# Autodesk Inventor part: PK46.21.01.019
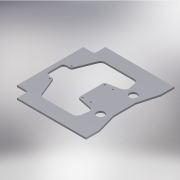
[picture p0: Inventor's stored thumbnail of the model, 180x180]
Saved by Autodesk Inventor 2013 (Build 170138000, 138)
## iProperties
Created: 2005-04
Part Number: PK46.21.01.019
Material: Steel, Mild
Document SubType Name: Modeling
Designer: salex
Manufacturer: Standard
Standards Organization: Custom
Density: 7.86 g/cm^3
Author: salex
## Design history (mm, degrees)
sketch "Эскиз1"
  geometry: L1 (0, 0)-(625, 0); L2 (625, 0)-(625, -120); L3 (625, -120)-(575, -300); L4 (575, -300)-(575, -500); L5 (0, 0)-(0, -100); L6 (0, -100)-(-100, -100); L7 (-100, -100)-(-100, -700); L8 (-60, -450)-(-60, -350); L9 (-30, -320)-(-5, -320); L10 (13.519, -307.552)-(79.848, -144.896); L11 (116.887, -120)-(381.959, -120); L12 (421.24, -152.446)-(432.521, -211.11); L13 (401.187, -257.867)-(290.027, -280.399); L14 (274, -300)-(274, -500); L15 (-32.529, -400)-(706.052, -400); L16 (401.187, -542.133)-(290.027, -519.601); L17 (421.24, -647.554)-(432.521, -588.89); L18 (116.887, -680)-(381.959, -680); L19 (0, -800)-(625, -800); L20 (625, -680)-(575, -500); L21 (0, -800)-(0, -700); L22 (0, -700)-(-100, -700); L23 (-30, -480)-(-5, -480); L24 (13.519, -492.448)-(79.848, -655.104); L25 (625, -800)-(625, -680); C1 r 6.5 at (294, -300); C2 r 6.5 at (294, -500); C3 r 35 at (505, -252); C4 r 35 at (505, -548); C5 r 6.5 at (-5, -300); C6 r 6.5 at (-5, -500); C7 r 6.5 at (368, -300); C8 r 6.5 at (368, -500); A1 r 30 centre (-30, -350) between (-30, -320) and (-60, -350); A2 r 20 centre (-5, -300) between (-5, -320) and (13.519, -307.552); A3 r 20 centre (294, -300) between (290.027, -280.399) and (274, -300); A4 r 40 centre (116.887, -160) between (116.887, -120) and (79.848, -144.896); A5 r 40 centre (381.959, -160) between (421.24, -152.446) and (381.959, -120); A6 r 40 centre (393.241, -218.664) between (401.187, -257.867) and (432.521, -211.11); A7 r 20 centre (294, -500) between (274, -500) and (290.027, -519.601); A8 r 40 centre (393.241, -581.336) between (432.521, -588.89) and (401.187, -542.133); A9 r 40 centre (116.887, -640) between (79.848, -655.104) and (116.887, -680); A10 r 40 centre (381.959, -640) between (381.959, -680) and (421.24, -647.554); A11 r 20 centre (-5, -500) between (13.519, -492.448) and (-5, -480); A12 r 30 centre (-30, -450) between (-60, -450) and (-30, -480); 6 further points
  constraints: 50 end point, 29 symmetric about line, 24 point on circle, 20 centre point, 12 point on line, 12 tangent, 6 equal radius, 6 parallel, 4 perpendicular, 2 coincident, 1 concentric, 1 horizontal, 9 other
  dimensions: "d0" = 725 distance between parallel lines of L2 L7; "d1" = 120 distance of L1.end L2.end; "d2" = 675 distance between parallel lines of L4 L7; "d3" = 300 distance from line of L3.end L1; "d4" = 100 distance of L1.start L5.end; "d5" = 100 distance of L5.end L6.end; "d6" = 325 distance of point (90, -120) point (415, -120); "d7" = 350 horizontal distance of point (440, -250) point (90, -120); "d9" = 800 diameter of L1 L15; "d10" = 560 diameter of L11 L15; "d12" = 20 radius of A2; "d13" = 20 radius of A3; "d15" = 13 diameter of C1 (= d14); "d19" = 130 distance from line of point (440, -250) L11; "d20" = 40 distance between parallel lines of L8 L7; "d23" = 30 radius of A1; "d24" = 40 radius of A4; "d25" = 296 diameter of C3.centre L15; "d26" = 70 diameter of C3; "d27" = 120 distance from line of C3.centre L2; "d32" = 0 horizontal distance of C5.centre C6.centre; "d33" = 299 distance of C1.centre C5.centre; "d35" = 95 distance from line of C6.centre L7; "d36" = 200 distance of C5.centre C6.centre; "d37" = 0 vertical distance of C1.centre C5.centre; "d38" = 200 diameter of C5.centre L15; "d39" = 190 distance from line of point (90, -120) L7; "d40" = 0 vertical distance of C7.centre C5.centre; "d41" = 0 vertical distance of C8.centre C2.centre; "d42" = 0 horizontal distance of C7.centre C8.centre; "d43" = 373 distance of C5.centre C7.centre
extrude "Выдавливание1" new body sketch "Эскиз1" distance "d28" = 16; taper "d29" = 0 deg
fillet "Сопряжение1" dims "d34" = 20
body "Solid1"
other parameters: "d14" = 13
